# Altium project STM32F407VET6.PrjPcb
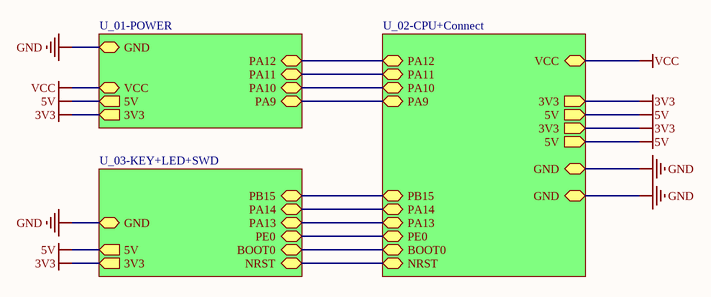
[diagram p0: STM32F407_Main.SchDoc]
4 sheets, 44 parts. Net scope: hierarchical (ports join the sheet entries above them; power ports are global).
Board file: PCB2.PcbDoc
Sheets:
  STM32F407_Main.SchDoc
    U_01-POWER = 01-POWER.SchDoc
    U_02-CPU+Connect = 02-CPU+Connect.SchDoc
    U_03-KEY+LED+SWD = 03-KEY+LED+SWD.SchDoc

## Sheet STM32F407_Main.SchDoc
size A4; SheetNumber: 1; SheetTotal: 4

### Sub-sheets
U_01-POWER = 01-POWER.SchDoc: 3V3 (out), GND (bidir), 5V (out), VCC (bidir), PA10 (bidir), PA9 (bidir), PA12 (bidir), PA11 (bidir)
U_02-CPU+Connect = 02-CPU+Connect.SchDoc: 3V3 (out), GND (bidir), 5V (out), NRST (bidir), PB15 (bidir), BOOT0 (bidir), PE0 (bidir), PA13 (bidir), PA14 (bidir), 3V3 (out), GND (bidir), 5V (out), VCC (bidir), PA10 (bidir), PA9 (bidir), PA12 (bidir), PA11 (bidir)
U_03-KEY+LED+SWD = 03-KEY+LED+SWD.SchDoc: 3V3 (out), GND (bidir), 5V (out), NRST (bidir), PB15 (bidir), BOOT0 (bidir), PE0 (bidir), PA13 (bidir), PA14 (bidir)

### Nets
3V3: sheet U_01-POWER/3V3, sheet U_02-CPU+Connect/3V3, sheet U_02-CPU+Connect/3V3, sheet U_03-KEY+LED+SWD/3V3
5V: sheet U_01-POWER/5V, sheet U_02-CPU+Connect/5V, sheet U_02-CPU+Connect/5V, sheet U_03-KEY+LED+SWD/5V
GND: sheet U_01-POWER/GND, sheet U_02-CPU+Connect/GND, sheet U_02-CPU+Connect/GND, sheet U_03-KEY+LED+SWD/GND
VCC: sheet U_01-POWER/VCC, sheet U_02-CPU+Connect/VCC
BOOT0: sheet U_02-CPU+Connect/BOOT0, sheet U_03-KEY+LED+SWD/BOOT0
NRST: sheet U_02-CPU+Connect/NRST, sheet U_03-KEY+LED+SWD/NRST
PA9: sheet U_01-POWER/PA9, sheet U_02-CPU+Connect/PA9
PA10: sheet U_01-POWER/PA10, sheet U_02-CPU+Connect/PA10
PA11: sheet U_01-POWER/PA11, sheet U_02-CPU+Connect/PA11
PA12: sheet U_01-POWER/PA12, sheet U_02-CPU+Connect/PA12
PA13: sheet U_02-CPU+Connect/PA13, sheet U_03-KEY+LED+SWD/PA13
PA14: sheet U_02-CPU+Connect/PA14, sheet U_03-KEY+LED+SWD/PA14
PB15: sheet U_02-CPU+Connect/PB15, sheet U_03-KEY+LED+SWD/PB15
PE0: sheet U_02-CPU+Connect/PE0, sheet U_03-KEY+LED+SWD/PE0

## Sheet 01-POWER.SchDoc
size A4; SheetNumber: 2; SheetTotal: 4
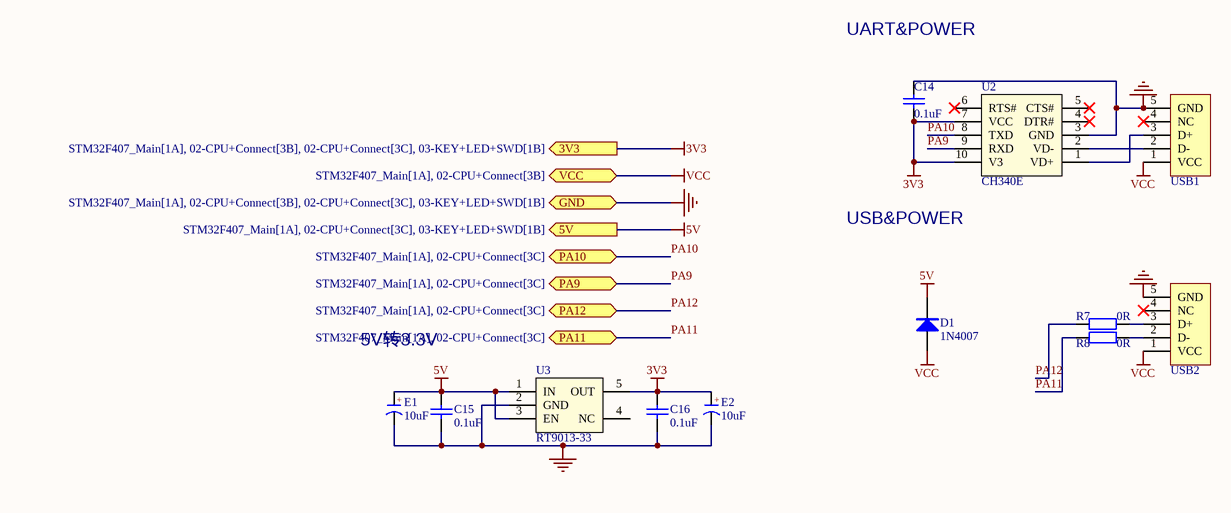
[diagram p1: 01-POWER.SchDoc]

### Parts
C14  0.1uF  [C 0402_L]
C15  0.1uF  [C 0402_L]
C16  0.1uF  [C 0402_L]
D1  1N4007  [SOD-123]
E1  10uF  [CD A(3216)]
E2  10uF  [CD A(3216)]
R7  0R  [R 0402_L]
R8  0R  [R 0402_L]
U2  CH340E  [MSOP10_L]
U3  RT9013-33  [SOT23-5N]
USB1  USB  [USB-MICRO_E]  (value not drawn)
USB2  USB  [USB-MICRO_E]  (value not drawn)

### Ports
3V3 (out, see STM32F407_Main[1A], 02-CPU+Connect[3B], 02-CPU+Connect[3C], 03-KEY+LED+SWD[1B]), 5V (out, see STM32F407_Main[1A], 02-CPU+Connect[3C], 03-KEY+LED+SWD[1B]), GND (bidir, see STM32F407_Main[1A], 02-CPU+Connect[3B], 02-CPU+Connect[3C], 03-KEY+LED+SWD[1B]), PA9 (bidir, see STM32F407_Main[1A], 02-CPU+Connect[3C]), PA10 (bidir, see STM32F407_Main[1A], 02-CPU+Connect[3C]), PA11 (bidir, see STM32F407_Main[1A], 02-CPU+Connect[3C]), PA12 (bidir, see STM32F407_Main[1A], 02-CPU+Connect[3C]), VCC (bidir, see STM32F407_Main[1A], 02-CPU+Connect[3B])

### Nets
3V3: C14.2 C16.2 E2.1(A) U2.7(VCC) U2.10(V3) U3.5(OUT) ; port 3V3
5V: C15.2 D1.2(K) E1.1(A) U3.1(IN) U3.3(EN) ; port 5V
GND: C14.1 C15.1 C16.1 E1.2(K) E2.2(K) U2.3(GND) U3.2(GND) USB1.5(GND) USB2.5(GND) ; port GND
VCC: D1.1(A) USB1.1(VCC) USB2.1(VCC) ; port VCC
PA9: U2.9(RXD) ; port PA9
PA10: U2.8(TXD) ; port PA10
PA11: R8.2 ; port PA11
PA12: R7.2 ; port PA12
NetR7_1: R7.1 USB2.3(D+)
NetR8_1: R8.1 USB2.2(D-)
NetU2_1: U2.1(VD+) USB1.3(D+)
NetU2_2: U2.2(VD-) USB1.2(D-)

Not connected (* = marked no-connect by the designer): U2 4(DTR#)* 5(CTS#)* 6(RTS#)*; U3 4(NC); USB1 4(NC)*; USB2 4(NC)*

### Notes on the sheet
- UART&POWER
- USB&POWER
- 5V转3.3V

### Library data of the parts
C14-C16 = Cap
D1 = 1N4007: 整流二极管
E1 E2 = C-CD: 贴片钽电容
R7 R8 = Res

## Sheet 02-CPU+Connect.SchDoc
size A4; SheetNumber: 3; SheetTotal: 4
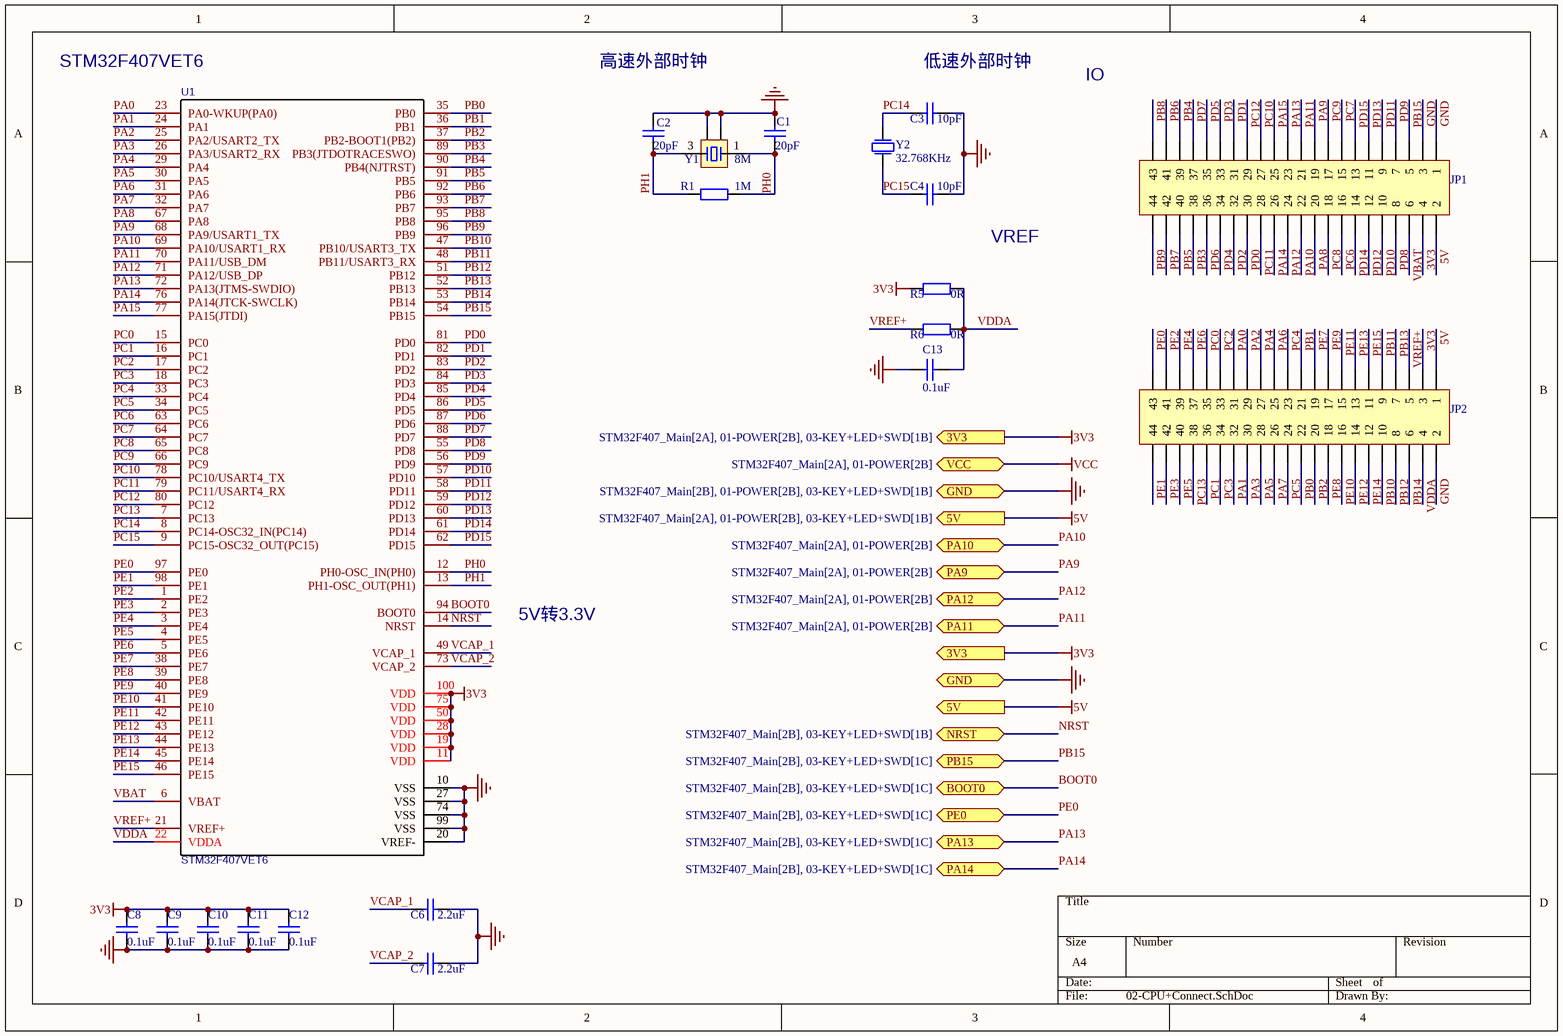
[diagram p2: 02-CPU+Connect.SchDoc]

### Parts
C1  20pF  [C 0402_L]
C2  20pF  [C 0402_L]
C3  10pF  [C 0402_L]
C4  10pF  [C 0402_L]
C6  2.2uF  [C 0402_L]
C7  2.2uF  [C 0402_L]
C8  0.1uF  [C 0402_L]
C9  0.1uF  [C 0402_L]
C10  0.1uF  [C 0402_L]
C11  0.1uF  [C 0402_L]
C12  0.1uF  [C 0402_L]
C13  0.1uF  [C 0402_L]
JP1  Header 2x22  [HDR2.54-LI-2x22P]  (value not drawn)
JP2  Header 2x22  [HDR2.54-LI-2x22P]  (value not drawn)
R1  1M  [R 0402_L]
R5  0R  [R 0402_L]
R6  0R  [R 0402_L]
U1  STM32F407VET6  [LQFP100 14x14_N]
Y1  8M  [OSC 3225-4P]
Y2  32.768KHz  [FC135-3.2X1.5]

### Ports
3V3 (out, see STM32F407_Main[2A], 01-POWER[2B], 03-KEY+LED+SWD[1B]), 5V (out, see STM32F407_Main[2A], 01-POWER[2B], 03-KEY+LED+SWD[1B]), BOOT0 (bidir, see STM32F407_Main[2B], 03-KEY+LED+SWD[1C]), GND (bidir, see STM32F407_Main[2B], 01-POWER[2B], 03-KEY+LED+SWD[1B]), NRST (bidir, see STM32F407_Main[2B], 03-KEY+LED+SWD[1B]), PA9 (bidir, see STM32F407_Main[2A], 01-POWER[2B]), PA10 (bidir, see STM32F407_Main[2A], 01-POWER[2B]), PA11 (bidir, see STM32F407_Main[2A], 01-POWER[2B]), PA12 (bidir, see STM32F407_Main[2A], 01-POWER[2B]), PA13 (bidir, see STM32F407_Main[2B], 03-KEY+LED+SWD[1C]), PA14 (bidir, see STM32F407_Main[2B], 03-KEY+LED+SWD[1C]), PB15 (bidir, see STM32F407_Main[2B], 03-KEY+LED+SWD[1C]), PE0 (bidir, see STM32F407_Main[2B], 03-KEY+LED+SWD[1C]), VCC (bidir, see STM32F407_Main[2A], 01-POWER[2B])

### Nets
3V3: C8.1 C9.1 C10.1 C11.1 C12.1 JP1.4 JP2.3 R5.2 U1.11(VDD) U1.19(VDD) U1.28(VDD) U1.50(VDD) U1.75(VDD) U1.100(VDD) ; port 3V3
5V: JP1.2 JP2.1 ; port 5V
GND: C1.1 C2.1 C3.1 C4.1 C6.1 C7.1 C8.2 C9.2 C10.2 C11.2 C12.2 C13.1 JP1.1 JP1.3 JP2.2 U1.10(VSS) U1.20(VREF-) U1.27(VSS) U1.74(VSS) U1.99(VSS) Y1.2 Y1.4 ; port GND
BOOT0: U1.94(BOOT0) ; port BOOT0
NRST: U1.14(NRST) ; port NRST
PA0: JP2.31 U1.23(PA0-WKUP(PA0))
PA1: JP2.32 U1.24(PA1)
PA2: JP2.29 U1.25(PA2/USART2_TX)
PA3: JP2.30 U1.26(PA3/USART2_RX)
PA4: JP2.27 U1.29(PA4)
PA5: JP2.28 U1.30(PA5)
PA6: JP2.25 U1.31(PA6)
PA7: JP2.26 U1.32(PA7)
PA8: JP1.20 U1.67(PA8)
PA9: JP1.19 U1.68(PA9/USART1_TX) ; port PA9
PA10: JP1.22 U1.69(PA10/USART1_RX) ; port PA10
PA11: JP1.21 U1.70(PA11/USB_DM) ; port PA11
PA12: JP1.24 U1.71(PA12/USB_DP) ; port PA12
PA13: JP1.23 U1.72(PA13(JTMS-SWDIO)) ; port PA13
PA14: JP1.26 U1.76(PA14(JTCK-SWCLK)) ; port PA14
PA15: JP1.25 U1.77(PA15(JTDI))
PB0: JP2.22 U1.35(PB0)
PB1: JP2.21 U1.36(PB1)
PB2: JP2.20 U1.37(PB2-BOOT1(PB2))
PB3: JP1.38 U1.89(PB3(JTDOTRACESWO))
PB4: JP1.39 U1.90(PB4(NJTRST))
PB5: JP1.40 U1.91(PB5)
PB6: JP1.41 U1.92(PB6)
PB7: JP1.42 U1.93(PB7)
PB8: JP1.43 U1.95(PB8)
PB9: JP1.44 U1.96(PB9)
PB10: JP2.10 U1.47(PB10/USART3_TX)
PB11: JP2.9 U1.48(PB11/USART3_RX)
PB12: JP2.8 U1.51(PB12)
PB13: JP2.7 U1.52(PB13)
PB14: JP2.6 U1.53(PB14)
PB15: JP1.5 U1.54(PB15) ; port PB15
PC0: JP2.35 U1.15(PC0)
PC1: JP2.36 U1.16(PC1)
PC2: JP2.33 U1.17(PC2)
PC3: JP2.34 U1.18(PC3)
PC4: JP2.23 U1.33(PC4)
PC5: JP2.24 U1.34(PC5)
PC6: JP1.16 U1.63(PC6)
PC7: JP1.15 U1.64(PC7)
PC8: JP1.18 U1.65(PC8)
PC9: JP1.17 U1.66(PC9)
PC10: JP1.27 U1.78(PC10/USART4_TX)
PC11: JP1.28 U1.79(PC11/USART4_RX)
PC12: JP1.29 U1.80(PC12)
PC13: JP2.38 U1.7(PC13)
PC14: C3.2 U1.8(PC14-OSC32_IN(PC14)) Y2.1(P1)
PC15: C4.2 U1.9(PC15-OSC32_OUT(PC15)) Y2.2(P2)
PD0: JP1.30 U1.81(PD0)
PD1: JP1.31 U1.82(PD1)
PD2: JP1.32 U1.83(PD2)
PD3: JP1.33 U1.84(PD3)
PD4: JP1.34 U1.85(PD4)
PD5: JP1.35 U1.86(PD5)
PD6: JP1.36 U1.87(PD6)
PD7: JP1.37 U1.88(PD7)
PD8: JP1.8 U1.55(PD8)
PD9: JP1.7 U1.56(PD9)
PD10: JP1.10 U1.57(PD10)
PD11: JP1.9 U1.58(PD11)
PD12: JP1.12 U1.59(PD12)
PD13: JP1.11 U1.60(PD13)
PD14: JP1.14 U1.61(PD14)
PD15: JP1.13 U1.62(PD15)
PE0: JP2.43 U1.97(PE0) ; port PE0
PE1: JP2.44 U1.98(PE1)
PE2: JP2.41 U1.1(PE2)
PE3: JP2.42 U1.2(PE3)
PE4: JP2.39 U1.3(PE4)
PE5: JP2.40 U1.4(PE5)
PE6: JP2.37 U1.5(PE6)
PE7: JP2.19 U1.38(PE7)
PE8: JP2.18 U1.39(PE8)
PE9: JP2.17 U1.40(PE9)
PE10: JP2.16 U1.41(PE10)
PE11: JP2.15 U1.42(PE11)
PE12: JP2.14 U1.43(PE12)
PE13: JP2.13 U1.44(PE13)
PE14: JP2.12 U1.45(PE14)
PE15: JP2.11 U1.46(PE15)
PH0: C1.2 R1.1 U1.12(PH0-OSC_IN(PH0)) Y1.1
PH1: C2.2 R1.2 U1.13(PH1-OSC_OUT(PH1)) Y1.3
VBAT: JP1.6 U1.6(VBAT)
VCAP_1: C6.2 U1.49(VCAP_1)
VCAP_2: C7.2 U1.73(VCAP_2)
VDDA: C13.2 JP2.4 R5.1 R6.1 U1.22(VDDA)
VREF+: JP2.5 R6.2 U1.21(VREF+)

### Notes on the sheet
- (near U1) STM32F407VET6
- 高速外部时钟
- (near C3) 低速外部时钟
- IO
- VREF
- 5V转3.3V

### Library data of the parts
C1-C4 C6-C13 = Cap
JP1 JP2 = Header 2x22: 2x22P接插件; BOM名称: 20*2P接插件
R1 R5 R6 = Res
U1 = STM32F407VET6: BOM_Manufacturer: ST; subpart_no: 1; tags: STM32
Y1 = XTAL-4P: 4脚无源晶振; 负载电容: CL20pF
Y2 = XTAL-2P

## Sheet 03-KEY+LED+SWD.SchDoc
size A4; SheetNumber: 4; SheetTotal: 4
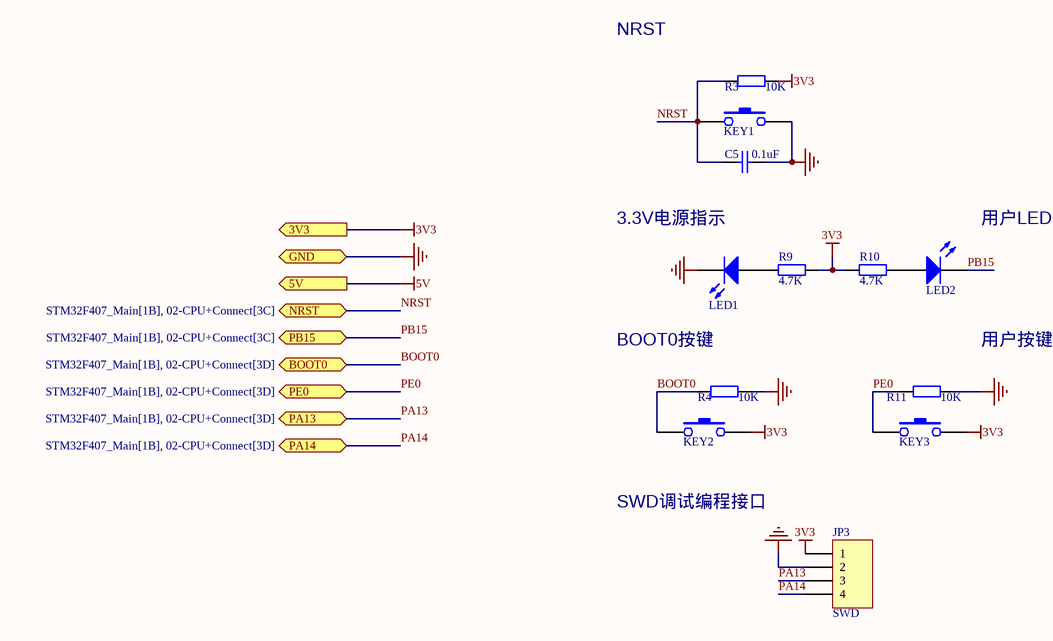
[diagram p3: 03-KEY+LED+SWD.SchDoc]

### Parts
C5  0.1uF  [C 0402_L]
JP3  SWD  [HDR2.54-WS-4P]
KEY1  KEY  [SWT3*4]  (value not drawn)
KEY2  KEY  [SWT3*4]  (value not drawn)
KEY3  KEY  [SWT3*4]  (value not drawn)
LED1  LED  [LED 0603]  (value not drawn)
LED2  LED  [LED 0603]  (value not drawn)
R3  10K  [R 0402_L]
R4  10K  [R 0402_L]
R9  4.7K  [R 0402_L]
R10  4.7K  [R 0402_L]
R11  10K  [R 0402_L]

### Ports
3V3 (out, see STM32F407_Main[1B], 01-POWER[2B], 02-CPU+Connect[3B], 02-CPU+Connect[3C]), 5V (out, see STM32F407_Main[1B], 01-POWER[2B], 02-CPU+Connect[3C]), BOOT0 (bidir, see STM32F407_Main[1B], 02-CPU+Connect[3D]), GND (bidir, see STM32F407_Main[1B], 01-POWER[2B], 02-CPU+Connect[3B], 02-CPU+Connect[3C]), NRST (bidir, see STM32F407_Main[1B], 02-CPU+Connect[3C]), PA13 (bidir, see STM32F407_Main[1B], 02-CPU+Connect[3D]), PA14 (bidir, see STM32F407_Main[1B], 02-CPU+Connect[3D]), PB15 (bidir, see STM32F407_Main[1B], 02-CPU+Connect[3C]), PE0 (bidir, see STM32F407_Main[1B], 02-CPU+Connect[3D])

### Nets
3V3: JP3.1 KEY2.2 KEY3.2 R3.1 R9.1 R10.1 ; port 3V3
GND: C5.1 JP3.2 KEY1.2 LED1.2(K) R4.1 R11.1 ; port GND
BOOT0: KEY2.1 R4.2 ; port BOOT0
NRST: C5.2 KEY1.1 R3.2 ; port NRST
PA13: JP3.3 ; port PA13
PA14: JP3.4 ; port PA14
PB15: LED2.2(K) ; port PB15
PE0: KEY3.1 R11.2 ; port PE0
NetLED1_1: LED1.1(A) R9.2
NetLED2_1: LED2.1(A) R10.2

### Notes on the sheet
- NRST
- 3.3V电源指示
- 用户LED
- BOOT0按键
- 用户按键
- SWD调试编程接口

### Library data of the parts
C5 = Cap
JP3 = Header 1*4
R3 R4 R9-R11 = Res

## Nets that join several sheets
3V3: 01-POWER (6 pins), 02-CPU+Connect (14 pins), 03-KEY+LED+SWD (6 pins)
5V: 01-POWER (5 pins), 02-CPU+Connect (JP1.2 JP2.1)
GND: 01-POWER (9 pins), 02-CPU+Connect (22 pins), 03-KEY+LED+SWD (6 pins)
BOOT0: 02-CPU+Connect (U1.94), 03-KEY+LED+SWD (KEY2.1 R4.2)
NRST: 02-CPU+Connect (U1.14), 03-KEY+LED+SWD (C5.2 KEY1.1 R3.2)
PA9: 01-POWER (U2.9), 02-CPU+Connect (JP1.19 U1.68)
PA10: 01-POWER (U2.8), 02-CPU+Connect (JP1.22 U1.69)
PA11: 01-POWER (R8.2), 02-CPU+Connect (JP1.21 U1.70)
PA12: 01-POWER (R7.2), 02-CPU+Connect (JP1.24 U1.71)
PA13: 02-CPU+Connect (JP1.23 U1.72), 03-KEY+LED+SWD (JP3.3)
PA14: 02-CPU+Connect (JP1.26 U1.76), 03-KEY+LED+SWD (JP3.4)
PB15: 02-CPU+Connect (JP1.5 U1.54), 03-KEY+LED+SWD (LED2.2)
PE0: 02-CPU+Connect (JP2.43 U1.97), 03-KEY+LED+SWD (KEY3.1 R11.2)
